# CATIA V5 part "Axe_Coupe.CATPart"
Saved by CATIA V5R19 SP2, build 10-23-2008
Part number: Axe_Coupe
Bounding box of the stored display mesh (mm): x 0 to 3, y -3 to 3, z -2.853 to 2.853
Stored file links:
  G:\EU_thinkMotion\CFAO_2010\MMS_groupe3\MMS_groupe3\A reprendre\lletoffe\lletoffe_Thinkmotion_CFAO\Modèle Catia\Axe_Coupe.CATPart
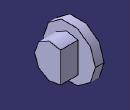
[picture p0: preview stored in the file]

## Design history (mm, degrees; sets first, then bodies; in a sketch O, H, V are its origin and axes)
Parameters
  Epaisseur = 1 mm
Set1
  Point1: (0, 0, 0)
  Point2: (1, 0, 0)
  Line1: type PtPt, FirstPoint Point1, SecondPoint Point2, Start 10, End 10
  Plane1: type Offset, RefPlane yz-plane, Offset 1 {= Epaisseur}
  Plane2: type Offset, RefPlane Plane1, Offset 2 {= 2*Epaisseur}
  Sketch1 on yz-plane, origin (0, 0, 0), H (0, 1, 0), V (0, 0, 1)
    circle A1 centre (0, 0) radius 3
    reference projected point E1 (0, 0) from Line1
    radius A1 = 3
    concentricity: E1 A1
  Sketch2 on Plane1, origin (1, 0, 0), H (0, 1, 0), V (0, 0, 1)
    arc A1 centre (0, 0) radius 2 from (1, 1.7321) to (1, -1.7321) ccw
    line L1 (1, 1.7321) -> (1, -1.7321)
    reference projected point E1 (0, 0) from Line1
    reference projected point E2 (0, 0) from Line1
    radius A1 = 2
    distance L1 E2 = 1
    vertical: L1 V
    concentricity: A1 E1
Body1 (main body)
  Pad1: profile Sketch1, direction (1, 0, 0), up to Plane1
  Pad2: profile Sketch2, direction (1, 0, 0), up to Plane2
